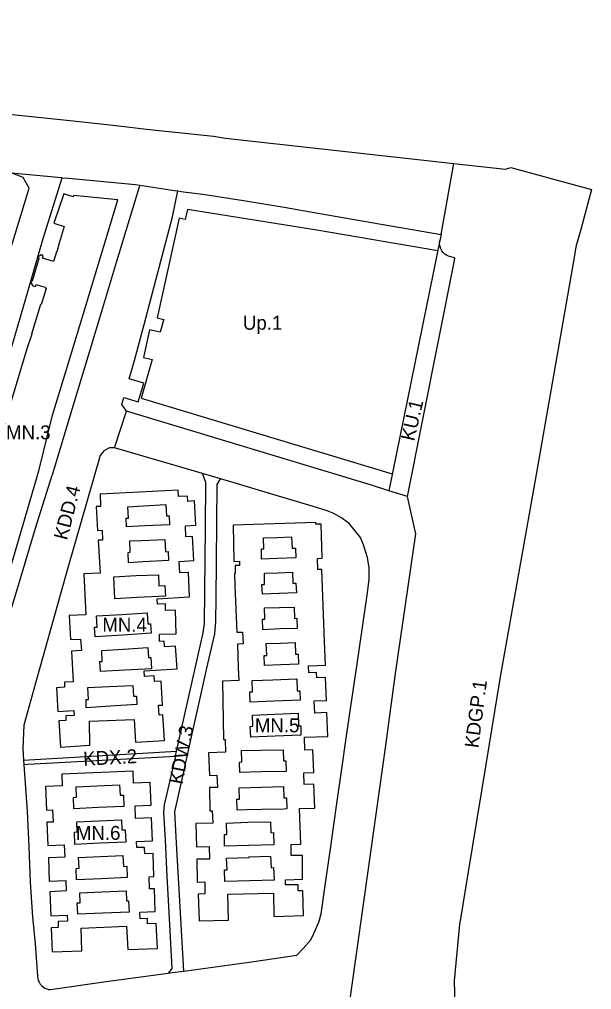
# Model space of a CAD drawing. Extents: x 7419601 to 7420547, y 5548907 to 5549873.
# Drawn here: x 7420244.8 to 7420450.1, y 5549175.5 to 5549523.4 of the extents above; entities that cross this region are included whole.
import ezdxf

# ---------------------------------------------------------------- set-up
doc = ezdxf.new("R2010")
doc.units = 0
for name, color, linetype in [('LIN_linie_rozgraniczajace', 7, 'Continuous'), ('LIN_nieprzekraczalna linia zabudowy', 7, 'Continuous'), ('LIN_obowiązująca linia zabudowy', 7, 'Continuous'), ('TXT_opisy_przeznaczen', 7, 'Continuous')]:
    doc.layers.add(name, color=color, linetype=linetype)

msp = doc.modelspace()

# ---------------------------------------------------------------- linework, layer by layer
at = {"layer": 'LIN_linie_rozgraniczajace'}
for p, q in [((7420396.11, 5549446.33), (7420400.67, 5549471.75)), ((7420241.79, 5549468.35), (7420259.85, 5549466.7)), ((7420287.99, 5549464.04), (7420300.43, 5549462.1)), ((7420384, 5549352.39), (7420400.85, 5549436.39)), ((7420278.89, 5549369.84), (7420283.23, 5549382.9)), ((7420300.76, 5549259.23), (7420301.19, 5549261.03)), ((7420246.31, 5549257.75), (7420246.41, 5549256.23)), ((7420299.62, 5549181.6), (7420303.74, 5549182.12))]:
    msp.add_line(p, q, dxfattribs=at)
for points in [[(7419989.52, 5549523.43), (7419998.15, 5549516.44), (7420007.04, 5549512.18), (7420016.72, 5549508.44), (7420026.26, 5549505.43), (7420036.29, 5549503.84), (7420042.96, 5549509.97), (7420115.64, 5549502.24), (7420186.48, 5549494.96), (7420230.69, 5549490.47), (7420266.36, 5549486.86), (7420280.44, 5549485.21), (7420290.37, 5549484.05), (7420314.5, 5549481.58), (7420318.73, 5549480.82), (7420355.46, 5549476.76), (7420369.45, 5549475.22), (7420400.67, 5549471.75), (7420403.92, 5549471.39)], [(7420403.92, 5549471.39), (7420419.25, 5549469.69), (7420421.09, 5549470.34), (7420450.13, 5549462.41), (7420446.2, 5549448.05), (7420444.52, 5549441.88), (7420443.96, 5549438.71), (7420430.19, 5549360.25), (7420417.35, 5549287.69), (7420412.11, 5549256.18), (7420405.69, 5549217.05), (7420402.97, 5549200.21), (7420402.76, 5549198.92), (7420400.82, 5549178.61), (7420401.26, 5549160.65)], [(7420195.45, 5549293.66), (7420198.05, 5549299.11), (7420211.79, 5549343.46), (7420248.32, 5549462.89), (7420246.2, 5549466.76), (7420241.79, 5549468.35)], [(7420206.16, 5549288.67), (7420206.36, 5549290.05), (7420206.43, 5549291.1), (7420208.23, 5549296.04), (7420216.58, 5549323.05), (7420224.94, 5549350.06), (7420234.81, 5549383.04), (7420242.46, 5549407.37), (7420247.93, 5549426.27), (7420253.33, 5549444.88), (7420260.19, 5549466.67)], [(7420259.85, 5549466.7), (7420260.19, 5549466.67), (7420262.42, 5549466.46), (7420286.5, 5549464.18), (7420287.99, 5549464.04)], [(7420287.99, 5549464.04), (7420287.55, 5549462.6), (7420279.67, 5549436.58), (7420274.2, 5549418.66), (7420268.11, 5549398.51), (7420262.51, 5549379.91), (7420256.57, 5549360.03)], [(7420283.23, 5549382.9), (7420281.52, 5549385.34), (7420282.26, 5549387.86), (7420287.43, 5549386.3), (7420289.46, 5549392.99), (7420284.21, 5549394.58), (7420286.13, 5549401.17), (7420289.57, 5549413.97), (7420299.73, 5549452.6), (7420301.62, 5549461.91)], [(7420300.43, 5549462.1), (7420301.62, 5549461.91), (7420303.73, 5549461.58), (7420310.56, 5549460.77), (7420325.18, 5549458.43), (7420339.8, 5549456.09), (7420352.55, 5549453.78), (7420364.34, 5549451.77), (7420371.11, 5549450.65), (7420396.11, 5549446.33)], [(7420396.11, 5549446.33), (7420395.67, 5549444.19), (7420394.71, 5549439.49)], [(7420399.48, 5549438.31), (7420398.79, 5549438.51), (7420398.11, 5549438.84), (7420397.46, 5549439.27), (7420396.87, 5549439.82), (7420396.37, 5549440.47), (7420395.99, 5549441.19), (7420395.73, 5549441.95), (7420395.59, 5549442.72), (7420395.58, 5549443.47), (7420395.67, 5549444.19)], [(7420394.71, 5549439.49), (7420377.33, 5549354.42)], [(7420400.85, 5549436.39), (7420401.07, 5549437.95), (7420399.48, 5549438.31)], [(7420384, 5549352.39), (7420377.33, 5549354.42), (7420371.19, 5549356.4), (7420283.23, 5549382.9)], [(7420278.89, 5549369.84), (7420277.08, 5549369.78), (7420275.1, 5549368.72), (7420273.73, 5549367.1), (7420262.22, 5549326.8), (7420251.18, 5549287.55), (7420246.42, 5549270.36), (7420246.06, 5549261.92), (7420246.31, 5549257.75)], [(7420310.55, 5549360.54), (7420278.89, 5549369.84)], [(7420301.19, 5549261.03), (7420310.79, 5549303.43), (7420311.25, 5549306.84), (7420311.6, 5549341.34), (7420311.68, 5549357.34), (7420310.55, 5549360.54)], [(7420317.35, 5549358.56), (7420316.92, 5549358.69), (7420310.55, 5549360.54)], [(7420233.06, 5549283.54), (7420239.1, 5549302.78), (7420244.83, 5549321.8), (7420250.62, 5549340.99), (7420256.57, 5549360.03)], [(7420303.74, 5549182.12), (7420301.96, 5549213.54), (7420301.29, 5549225.82), (7420300.62, 5549239.29), (7420303.41, 5549252.05), (7420306.31, 5549265.08), (7420309.15, 5549277.85), (7420312.1, 5549290.74), (7420314.92, 5549303.14), (7420315.33, 5549307.46), (7420315.39, 5549315.86), (7420315.52, 5549328.95), (7420315.8, 5549356.63), (7420316.1, 5549357.23), (7420316.92, 5549358.69)], [(7420303.74, 5549182.12), (7420328.1, 5549185.51), (7420344.33, 5549187.9), (7420346.61, 5549190.21), (7420349.38, 5549193.34), (7420350.43, 5549195.66), (7420352.2, 5549199.65), (7420353.04, 5549202.63), (7420354.83, 5549215.3), (7420356.65, 5549227.61), (7420358.45, 5549240.58), (7420360.35, 5549253.89), (7420362.2, 5549266.49), (7420364.06, 5549279.48), (7420365.98, 5549292.29), (7420367.91, 5549305.52), (7420369.65, 5549317.81), (7420370.33, 5549322.7), (7420370.27, 5549326.77), (7420369.76, 5549330.42), (7420368.23, 5549335.05), (7420367.17, 5549337.61), (7420363.18, 5549342.7), (7420360.17, 5549344.77), (7420357.58, 5549346.21), (7420355.21, 5549347.17), (7420349.83, 5549348.87), (7420336.52, 5549352.83), (7420319.45, 5549357.93), (7420317.35, 5549358.56)], [(7420360.96, 5549170.26), (7420363.21, 5549170.37), (7420376.18, 5549262.27), (7420379.7, 5549288.81), (7420387.03, 5549338.97), (7420384, 5549352.39)], [(7420246.31, 5549257.75), (7420301.19, 5549261.03)], [(7420246.41, 5549256.23), (7420247.83, 5549256.31), (7420272.38, 5549257.66), (7420300.76, 5549259.23)], [(7420300.76, 5549259.23), (7420296.8, 5549241.83), (7420296.49, 5549239), (7420297.05, 5549229.09), (7420297.74, 5549216.08), (7420298.45, 5549203.27), (7420299.54, 5549183.1), (7420298.13, 5549181.4)], [(7420246.41, 5549256.23), (7420247.53, 5549239.39), (7420248.17, 5549226.78), (7420248.63, 5549214.02), (7420249.46, 5549201.45), (7420250.41, 5549192.04), (7420251.27, 5549180.16)], [(7420251.27, 5549180.16), (7420251.36, 5549179.49), (7420251.55, 5549178.82), (7420251.84, 5549178.15), (7420252.24, 5549177.52), (7420252.72, 5549176.96), (7420253.29, 5549176.47), (7420253.92, 5549176.08), (7420254.59, 5549175.79), (7420255.26, 5549175.6), (7420255.93, 5549175.52)], [(7420255.93, 5549175.52), (7420275.89, 5549178.38), (7420298.13, 5549181.4), (7420299.62, 5549181.6)]]:
    msp.add_lwpolyline(points, dxfattribs=at)
at = {"layer": 'LIN_nieprzekraczalna linia zabudowy'}
msp.add_line((7420280.11, 5549458.76), (7420264.19, 5549460.26), dxfattribs=at)
for points in [[(7420264.19, 5549460.26), (7420264.06, 5549459.84), (7420260.74, 5549460.93), (7420257.17, 5549450.4), (7420260.88, 5549449.18), (7420259.09, 5549443.19), (7420258.18, 5549440.07), (7420258.11, 5549440.09), (7420257.08, 5549436.64), (7420255.5, 5549437.1), (7420253.1, 5549437.81), (7420253.35, 5549438.63), (7420252.75, 5549438.99), (7420251.49, 5549438.27), (7420251.8, 5549437.67), (7420249.39, 5549429.58), (7420248.79, 5549429.25), (7420249.67, 5549427.87), (7420250.56, 5549427.6), (7420250.79, 5549428.37), (7420252.75, 5549427.79), (7420254.1, 5549427.39), (7420254.03, 5549427.15), (7420254.4, 5549427.04), (7420253.67, 5549424.52), (7420252.59, 5549421.15), (7420252.38, 5549421.21), (7420249.16, 5549410.59), (7420249.2, 5549410.58), (7420247.52, 5549405.31), (7420235.77, 5549366.6)], [(7420239.92, 5549321.03), (7420240.53, 5549323.11), (7420251.8, 5549361.56), (7420256.72, 5549381.5), (7420262.37, 5549400.24), (7420268.46, 5549420.4), (7420280.11, 5549458.76)], [(7420305.1, 5549455.29), (7420304.32, 5549451.69), (7420302.12, 5549452.17), (7420294.22, 5549416.37), (7420296.57, 5549415.86), (7420296.32, 5549414.7), (7420295.32, 5549411.27), (7420291.46, 5549412.11), (7420289.31, 5549402.2), (7420292.48, 5549401.51), (7420288.43, 5549387.6)], [(7420394.91, 5549440.45), (7420351.57, 5549447.86), (7420305.1, 5549455.29)], [(7420288.43, 5549387.6), (7420378.56, 5549360.45)]]:
    msp.add_lwpolyline(points, dxfattribs=at)
at = {"layer": 'LIN_obowiązująca linia zabudowy'}
for p, q in [((7420301.74, 5549354.66), (7420273.82, 5549353.15)), ((7420273.82, 5549353.15), (7420273.93, 5549348.79)), ((7420301.92, 5549352.3), (7420301.74, 5549354.66)), ((7420305.14, 5549352.46), (7420301.92, 5549352.3)), ((7420305.27, 5549350.6), (7420305.14, 5549352.46)), ((7420307.65, 5549350.78), (7420305.27, 5549350.6)), ((7420308.14, 5549342.05), (7420307.65, 5549350.78)), ((7420273.93, 5549348.79), (7420272.33, 5549348.78)), ((7420272.33, 5549348.78), (7420272.86, 5549340.18)), ((7420351.15, 5549342.97), (7420321.49, 5549342.01)), ((7420351.16, 5549342.4), (7420351.15, 5549342.97)), ((7420272.86, 5549340.18), (7420274.51, 5549340.27)), ((7420274.51, 5549340.27), (7420274.66, 5549336.74)), ((7420304.36, 5549341.85), (7420308.14, 5549342.05)), ((7420304.48, 5549337.9), (7420304.36, 5549341.85)), ((7420321.49, 5549342.01), (7420321.74, 5549329.09)), ((7420353.06, 5549342.47), (7420351.16, 5549342.4)), ((7420353.44, 5549330.19), (7420353.06, 5549342.47)), ((7420274.66, 5549336.74), (7420273.04, 5549336.65)), ((7420273.04, 5549336.65), (7420273.75, 5549324.89)), ((7420306.92, 5549338.01), (7420304.48, 5549337.9)), ((7420307.36, 5549329.36), (7420306.92, 5549338.01)), ((7420302.11, 5549329.06), (7420307.36, 5549329.36)), ((7420302.38, 5549324.96), (7420302.11, 5549329.06)), ((7420321.74, 5549329.09), (7420323.72, 5549329.16)), ((7420323.72, 5549329.16), (7420323.78, 5549327.58)), ((7420351.77, 5549330.13), (7420353.44, 5549330.19)), ((7420351.91, 5549326.11), (7420351.77, 5549330.13)), ((7420323.78, 5549327.58), (7420322.22, 5549327.58)), ((7420322.22, 5549327.58), (7420322.22, 5549324.69)), ((7420353.37, 5549326.17), (7420351.91, 5549326.11)), ((7420354.31, 5549300.36), (7420353.37, 5549326.17)), ((7420273.75, 5549324.89), (7420267.88, 5549324.65)), ((7420267.88, 5549324.65), (7420268.62, 5549309.95)), ((7420305.42, 5549325.06), (7420302.38, 5549324.96)), ((7420305.84, 5549316.33), (7420305.42, 5549325.06)), ((7420322.22, 5549324.69), (7420321.99, 5549324.71)), ((7420321.99, 5549324.71), (7420322.1, 5549320.36)), ((7420322.1, 5549320.36), (7420322.81, 5549303.64)), ((7420294.22, 5549315.6), (7420305.84, 5549316.33)), ((7420294.3, 5549313.79), (7420294.22, 5549315.6)), ((7420297.21, 5549313.84), (7420294.3, 5549313.79)), ((7420297.24, 5549311.5), (7420297.21, 5549313.84)), ((7420300.85, 5549311.56), (7420297.24, 5549311.5)), ((7420300.99, 5549303.12), (7420300.85, 5549311.56)), ((7420268.62, 5549309.95), (7420262.64, 5549309.66)), ((7420262.64, 5549309.66), (7420263.17, 5549301.01)), ((7420263.17, 5549301.01), (7420266.77, 5549301.23)), ((7420266.77, 5549301.23), (7420267.02, 5549297.07)), ((7420295.02, 5549303.02), (7420300.99, 5549303.12)), ((7420295.06, 5549300.36), (7420295.02, 5549303.02)), ((7420322.81, 5549303.64), (7420324.87, 5549303.71)), ((7420324.87, 5549303.71), (7420325.08, 5549299.45)), ((7420296.74, 5549300.46), (7420295.06, 5549300.36)), ((7420296.87, 5549298.49), (7420296.74, 5549300.46)), ((7420300.85, 5549298.73), (7420296.87, 5549298.49)), ((7420301.35, 5549290.58), (7420300.85, 5549298.73)), ((7420325.08, 5549299.45), (7420323.03, 5549299.36)), ((7420323.03, 5549299.36), (7420323.34, 5549290.94)), ((7420354.59, 5549291.83), (7420354.31, 5549300.36)), ((7420267.02, 5549297.07), (7420263.52, 5549296.85)), ((7420263.52, 5549296.85), (7420264.05, 5549285.92)), ((7420289.62, 5549289.86), (7420301.35, 5549290.58)), ((7420323.34, 5549290.94), (7420323.53, 5549286.36)), ((7420348.53, 5549291.66), (7420354.59, 5549291.83)), ((7420348.63, 5549289.14), (7420348.53, 5549291.66)), ((7420289.64, 5549287.81), (7420289.62, 5549289.86)), ((7420293.11, 5549288.02), (7420289.64, 5549287.81)), ((7420293.24, 5549286.01), (7420293.11, 5549288.02)), ((7420351.46, 5549289.25), (7420348.63, 5549289.14)), ((7420351.54, 5549287.3), (7420351.46, 5549289.25)), ((7420354.61, 5549287.42), (7420351.54, 5549287.3)), ((7420354.95, 5549279.17), (7420354.61, 5549287.42)), ((7420261.01, 5549283.92), (7420258.15, 5549283.77)), ((7420258.15, 5549283.77), (7420258.61, 5549275.27)), ((7420264.05, 5549285.92), (7420260.93, 5549285.8)), ((7420260.93, 5549285.8), (7420261.01, 5549283.92)), ((7420295.61, 5549286.15), (7420293.24, 5549286.01)), ((7420296.13, 5549277.52), (7420295.61, 5549286.15)), ((7420323.53, 5549286.36), (7420317.63, 5549286.12)), ((7420317.63, 5549286.12), (7420318.09, 5549265.23)), ((7420294.72, 5549277.5), (7420296.13, 5549277.52)), ((7420294.95, 5549273.91), (7420294.72, 5549277.5)), ((7420350.58, 5549279.03), (7420354.95, 5549279.17)), ((7420350.78, 5549274.68), (7420350.58, 5549279.03)), ((7420258.61, 5549275.27), (7420264.32, 5549275.61)), ((7420264.39, 5549273.82), (7420261.44, 5549273.7)), ((7420261.44, 5549273.7), (7420261.51, 5549272.02)), ((7420264.32, 5549275.61), (7420264.39, 5549273.82)), ((7420296.31, 5549274), (7420294.95, 5549273.91)), ((7420296.91, 5549264.9), (7420296.31, 5549274)), ((7420355.13, 5549274.88), (7420350.78, 5549274.68)), ((7420355.52, 5549266.32), (7420355.13, 5549274.88)), ((7420261.51, 5549272.02), (7420258.97, 5549271.9)), ((7420258.97, 5549271.9), (7420259.49, 5549262.49)), ((7420269.98, 5549271.73), (7420285.93, 5549272.38)), ((7420270.12, 5549263.15), (7420269.98, 5549271.73)), ((7420285.93, 5549272.38), (7420286.47, 5549264.21)), ((7420347.08, 5549266.07), (7420355.52, 5549266.32)), ((7420259.49, 5549262.49), (7420270.12, 5549263.15)), ((7420286.47, 5549264.21), (7420296.91, 5549264.9)), ((7420318.09, 5549265.23), (7420318.6, 5549265.24)), ((7420318.6, 5549265.24), (7420318.8, 5549260.64)), ((7420347.25, 5549261.42), (7420347.08, 5549266.07)), ((7420318.8, 5549260.64), (7420312.7, 5549260.45)), ((7420312.7, 5549260.45), (7420313.06, 5549252.3)), ((7420350.08, 5549261.53), (7420347.25, 5549261.42)), ((7420350.39, 5549253.42), (7420350.08, 5549261.53)), ((7420285.59, 5549253.82), (7420259.97, 5549252.78)), ((7420259.97, 5549252.78), (7420260.13, 5549248.55)), ((7420285.76, 5549249.6), (7420285.59, 5549253.82)), ((7420313.06, 5549252.3), (7420315.66, 5549252.41)), ((7420315.66, 5549252.41), (7420315.85, 5549248.01)), ((7420346.81, 5549253.3), (7420350.39, 5549253.42)), ((7420346.98, 5549249.04), (7420346.81, 5549253.3)), ((7420291.67, 5549249.84), (7420285.76, 5549249.6)), ((7420292.08, 5549241.68), (7420291.67, 5549249.84)), ((7420350.5, 5549249.2), (7420346.98, 5549249.04)), ((7420350.8, 5549240.57), (7420350.5, 5549249.2)), ((7420260.13, 5549248.55), (7420254.16, 5549248.3)), ((7420254.16, 5549248.3), (7420254.48, 5549239.88)), ((7420315.85, 5549248.01), (7420312.96, 5549247.94)), ((7420312.96, 5549247.94), (7420313.14, 5549239.57)), ((7420254.48, 5549239.88), (7420256.72, 5549239.97)), ((7420256.72, 5549239.97), (7420256.88, 5549235.61)), ((7420286.31, 5549241.41), (7420292.08, 5549241.68)), ((7420286.5, 5549236.87), (7420286.31, 5549241.41)), ((7420313.14, 5549239.57), (7420313.97, 5549239.59)), ((7420313.97, 5549239.59), (7420314.15, 5549235.14)), ((7420345.29, 5549240.46), (7420350.8, 5549240.57)), ((7420345.77, 5549227.65), (7420345.29, 5549240.46)), ((7420256.88, 5549235.61), (7420254.68, 5549235.6)), ((7420254.68, 5549235.6), (7420255.02, 5549227.16)), ((7420292.2, 5549237.1), (7420286.5, 5549236.87)), ((7420292.55, 5549228.83), (7420292.2, 5549237.1)), ((7420314.15, 5549235.14), (7420308.09, 5549235.03)), ((7420308.09, 5549235.03), (7420308.37, 5549226.68)), ((7420286.86, 5549228.6), (7420292.55, 5549228.83)), ((7420286.95, 5549226.43), (7420286.86, 5549228.6)), ((7420255.02, 5549227.16), (7420260.89, 5549227.42)), ((7420260.89, 5549227.42), (7420261.07, 5549223.02)), ((7420289.7, 5549226.52), (7420286.95, 5549226.43)), ((7420289.79, 5549224.21), (7420289.7, 5549226.52)), ((7420308.37, 5549226.68), (7420312.86, 5549226.83)), ((7420312.86, 5549226.83), (7420313.01, 5549222.34)), ((7420342.36, 5549227.52), (7420345.77, 5549227.65)), ((7420342.36, 5549223.63), (7420342.36, 5549227.52)), ((7420261.07, 5549223.02), (7420255.29, 5549222.78)), ((7420255.29, 5549222.78), (7420255.48, 5549214.38)), ((7420292.77, 5549224.32), (7420289.79, 5549224.21)), ((7420293.06, 5549216.09), (7420292.77, 5549224.32)), ((7420313.01, 5549222.34), (7420308.52, 5549222.33)), ((7420308.52, 5549222.33), (7420308.63, 5549214.07)), ((7420346.44, 5549223.63), (7420342.36, 5549223.63)), ((7420346.44, 5549215.06), (7420346.44, 5549223.63)), ((7420255.48, 5549214.38), (7420261.44, 5549214.65)), ((7420261.44, 5549214.65), (7420261.6, 5549210.91)), ((7420291.33, 5549215.97), (7420293.06, 5549216.09)), ((7420291.5, 5549211.63), (7420291.33, 5549215.97)), ((7420308.63, 5549214.07), (7420311.28, 5549214.11)), ((7420311.28, 5549214.11), (7420311.33, 5549209.8)), ((7420340.27, 5549214.9), (7420346.44, 5549215.06)), ((7420340.29, 5549213.04), (7420340.27, 5549214.9)), ((7420261.6, 5549210.91), (7420255.7, 5549210.62)), ((7420255.7, 5549210.62), (7420256.04, 5549201.93)), ((7420293.26, 5549211.7), (7420291.5, 5549211.63)), ((7420293.57, 5549203.49), (7420293.26, 5549211.7)), ((7420344.83, 5549213.04), (7420340.29, 5549213.04)), ((7420344.88, 5549210.94), (7420344.83, 5549213.04)), ((7420346.5, 5549210.98), (7420344.88, 5549210.94)), ((7420346.73, 5549202.04), (7420346.5, 5549210.98)), ((7420311.33, 5549209.8), (7420308.96, 5549209.78)), ((7420308.96, 5549209.78), (7420309.27, 5549200.12)), ((7420319.54, 5549209.68), (7420335.97, 5549210.14)), ((7420319.82, 5549200.46), (7420319.54, 5549209.68)), ((7420335.97, 5549210.14), (7420336.12, 5549201.76)), ((7420287.99, 5549203.26), (7420293.57, 5549203.49)), ((7420256.04, 5549201.93), (7420261.95, 5549202.18)), ((7420262.04, 5549200.09), (7420258.65, 5549199.95)), ((7420261.95, 5549202.18), (7420262.04, 5549200.09)), ((7420288.09, 5549200.87), (7420287.99, 5549203.26)), ((7420290.75, 5549200.97), (7420288.09, 5549200.87)), ((7420290.82, 5549199.1), (7420290.75, 5549200.97)), ((7420309.27, 5549200.12), (7420319.82, 5549200.46)), ((7420336.12, 5549201.76), (7420346.73, 5549202.04)), ((7420258.74, 5549197.79), (7420256.21, 5549197.71)), ((7420256.21, 5549197.71), (7420256.54, 5549189.05)), ((7420258.65, 5549199.95), (7420258.74, 5549197.79)), ((7420266.94, 5549197.5), (7420283.23, 5549198.22)), ((7420267.15, 5549189.45), (7420266.94, 5549197.5)), ((7420283.23, 5549198.22), (7420283.71, 5549189.85)), ((7420293.86, 5549199.22), (7420290.82, 5549199.1)), ((7420294.4, 5549190.29), (7420293.86, 5549199.22)), ((7420283.71, 5549189.85), (7420294.4, 5549190.29)), ((7420256.54, 5549189.05), (7420267.15, 5549189.45))]:
    msp.add_line(p, q, dxfattribs=at)
for points in [[(7420283.23, 5549341.45), (7420283.11, 5549344.59), (7420283.89, 5549344.63), (7420283.76, 5549348.69), (7420289.38, 5549348.99), (7420297.31, 5549349.42), (7420297.55, 5549345.36), (7420298.58, 5549345.4), (7420298.71, 5549342.22), (7420289.77, 5549341.77)], [(7420283.99, 5549328.6), (7420283.83, 5549332.28), (7420284.56, 5549332.32), (7420284.4, 5549336.4), (7420288.62, 5549336.61), (7420297.02, 5549336.95), (7420297.17, 5549332.52), (7420298.22, 5549332.56), (7420298.31, 5549329.38), (7420289.08, 5549328.86)], [(7420331.67, 5549329.89), (7420331.62, 5549333.54), (7420332.54, 5549333.58), (7420332.39, 5549337.52), (7420337.28, 5549337.67), (7420342.44, 5549337.83), (7420342.64, 5549333.8), (7420343.81, 5549333.85), (7420343.96, 5549330.29), (7420337.38, 5549330.08)], [(7420279.06, 5549315.65), (7420278.73, 5549323.57), (7420286.64, 5549323.96), (7420294.66, 5549324.29), (7420294.83, 5549320.32), (7420296.96, 5549320.4), (7420297.17, 5549316.64), (7420287.06, 5549316.08)], [(7420332.7, 5549324.8), (7420337.61, 5549324.98), (7420342.76, 5549325.17), (7420342.93, 5549321.22), (7420344.03, 5549321.26), (7420344.24, 5549317.75), (7420337.97, 5549317.51), (7420332.02, 5549317.33), (7420331.84, 5549320.8), (7420332.79, 5549320.84)], [(7420332.79, 5549312.42), (7420338.12, 5549312.53), (7420343.38, 5549312.71), (7420343.51, 5549308.64), (7420344.4, 5549308.68), (7420344.52, 5549304.98), (7420338.33, 5549304.83), (7420332.09, 5549304.56), (7420331.97, 5549308.31), (7420332.92, 5549308.35)], [(7420271.94, 5549301.98), (7420271.75, 5549305.45), (7420272.71, 5549305.49), (7420272.48, 5549309.53), (7420281.57, 5549310.05), (7420290.68, 5549310.62), (7420290.92, 5549306.69), (7420291.83, 5549306.73), (7420292.04, 5549303.3), (7420281.91, 5549302.67)], [(7420273.87, 5549289.54), (7420273.69, 5549293.13), (7420274.54, 5549293.19), (7420274.42, 5549297.17), (7420282.19, 5549297.58), (7420290.91, 5549298.16), (7420291.12, 5549294.56), (7420292.01, 5549294.6), (7420292.19, 5549290.52), (7420282.66, 5549290.1)], [(7420333.4, 5549299.64), (7420338.47, 5549299.77), (7420343.73, 5549300.01), (7420343.91, 5549295.76), (7420344.83, 5549295.79), (7420344.94, 5549292.17), (7420338.57, 5549291.98), (7420332.77, 5549291.72), (7420332.65, 5549295.3), (7420333.57, 5549295.33)], [(7420328.26, 5549286.32), (7420335.73, 5549286.64), (7420344.31, 5549287), (7420344.49, 5549282.64), (7420345.37, 5549282.67), (7420345.51, 5549279.36), (7420336.12, 5549278.98), (7420327.56, 5549278.64), (7420327.44, 5549282.26), (7420328.42, 5549282.3)], [(7420268.81, 5549276.53), (7420268.72, 5549279.5), (7420269.6, 5549279.54), (7420269.38, 5549283.87), (7420276.97, 5549284.25), (7420285.49, 5549284.6), (7420285.72, 5549280.7), (7420286.76, 5549280.74), (7420286.9, 5549277.7), (7420277.33, 5549277.11)], [(7420328.43, 5549273.95), (7420336.28, 5549274.27), (7420344.79, 5549274.63), (7420344.99, 5549270.1), (7420345.76, 5549270.13), (7420345.8, 5549266.71), (7420336.53, 5549266.38), (7420327.79, 5549266.05), (7420327.62, 5549269.9), (7420328.53, 5549269.99)], [(7420324.51, 5549261.21), (7420331.29, 5549261.36), (7420339.43, 5549261.45), (7420339.56, 5549257.57), (7420340.42, 5549257.6), (7420340.55, 5549253.78), (7420331.55, 5549253.58), (7420323.87, 5549253.33), (7420323.78, 5549257.11), (7420324.61, 5549257.15)], [(7420264.37, 5549240.36), (7420264.15, 5549244.46), (7420265.29, 5549244.51), (7420265.14, 5549248.24), (7420272.72, 5549248.55), (7420280.76, 5549248.93), (7420280.93, 5549245.2), (7420282.12, 5549245.21), (7420282.31, 5549241.22), (7420273.01, 5549240.77)], [(7420323.67, 5549247.91), (7420331.65, 5549248.12), (7420339.58, 5549248.32), (7420339.74, 5549244.29), (7420340.6, 5549244.33), (7420340.76, 5549240.31), (7420339.66, 5549240.27), (7420331.79, 5549240.07), (7420326.54, 5549239.92), (7420322.9, 5549239.83), (7420322.82, 5549243.76), (7420323.77, 5549243.81)], [(7420264.72, 5549227.6), (7420264.54, 5549232), (7420265.58, 5549232.04), (7420265.43, 5549235.71), (7420273.25, 5549236.02), (7420281.45, 5549236.37), (7420281.59, 5549232.81), (7420282.74, 5549232.86), (7420282.95, 5549228.42), (7420273.66, 5549227.99)], [(7420319.05, 5549235.17), (7420326.76, 5549235.51), (7420334.89, 5549235.73), (7420335.02, 5549231.79), (7420335.94, 5549231.82), (7420336.09, 5549227.4), (7420327.17, 5549227.17), (7420318.43, 5549226.94), (7420318.36, 5549231.12), (7420319.23, 5549231.16)], [(7420265.3, 5549214.83), (7420265.12, 5549218.99), (7420266.23, 5549219.04), (7420265.99, 5549222.93), (7420273.88, 5549223.3), (7420281.95, 5549223.63), (7420282.11, 5549219.7), (7420283.32, 5549219.75), (7420283.51, 5549215.66), (7420274.27, 5549215.24)], [(7420319.15, 5549222.6), (7420327.19, 5549222.9), (7420327.18, 5549223.07), (7420334.91, 5549223.36), (7420335.08, 5549219.21), (7420336.03, 5549219.25), (7420336.2, 5549214.79), (7420327.53, 5549214.57), (7420318.54, 5549214.33), (7420318.37, 5549218.45), (7420319.3, 5549218.49)], [(7420265.73, 5549202.53), (7420265.56, 5549206.57), (7420266.64, 5549206.61), (7420266.5, 5549210.27), (7420274.4, 5549210.57), (7420283.12, 5549210.94), (7420283.27, 5549207.35), (7420284, 5549207.38), (7420284.16, 5549203.29), (7420274.78, 5549202.92)]]:
    msp.add_lwpolyline(points, close=True, dxfattribs=at)

# ---------------------------------------------------------------- texts
at = {"layer": 'TXT_opisy_przeznaczen'}
for s, p in [('Up.1', (7420325, 5549412.15)), ('MN.3', (7420240.01, 5549372.85)), ('MN.4', (7420274.55, 5549303.84)), ('MN.5', (7420329.3, 5549267.78)), ('MN.6', (7420265.07, 5549229.21))]:
    msp.add_text(s, height=5, dxfattribs=at).set_placement(p)
for s, rotation, p in [('KU.1', 77, (7420386.44, 5549371.96)), ('KDD.4', 75.6022, (7420261.89, 5549336.44)), ('KDGP.1', 82.6417, (7420409.48, 5549261.94)), ('KDW.3', 79, (7420303.29, 5549248.87)), ('KDX.2', 3, (7420267.83, 5549255.76))]:
    msp.add_text(s, height=5, rotation=rotation, dxfattribs=at).set_placement(p)

doc.saveas('drawing.dxf')
